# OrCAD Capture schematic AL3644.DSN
size D
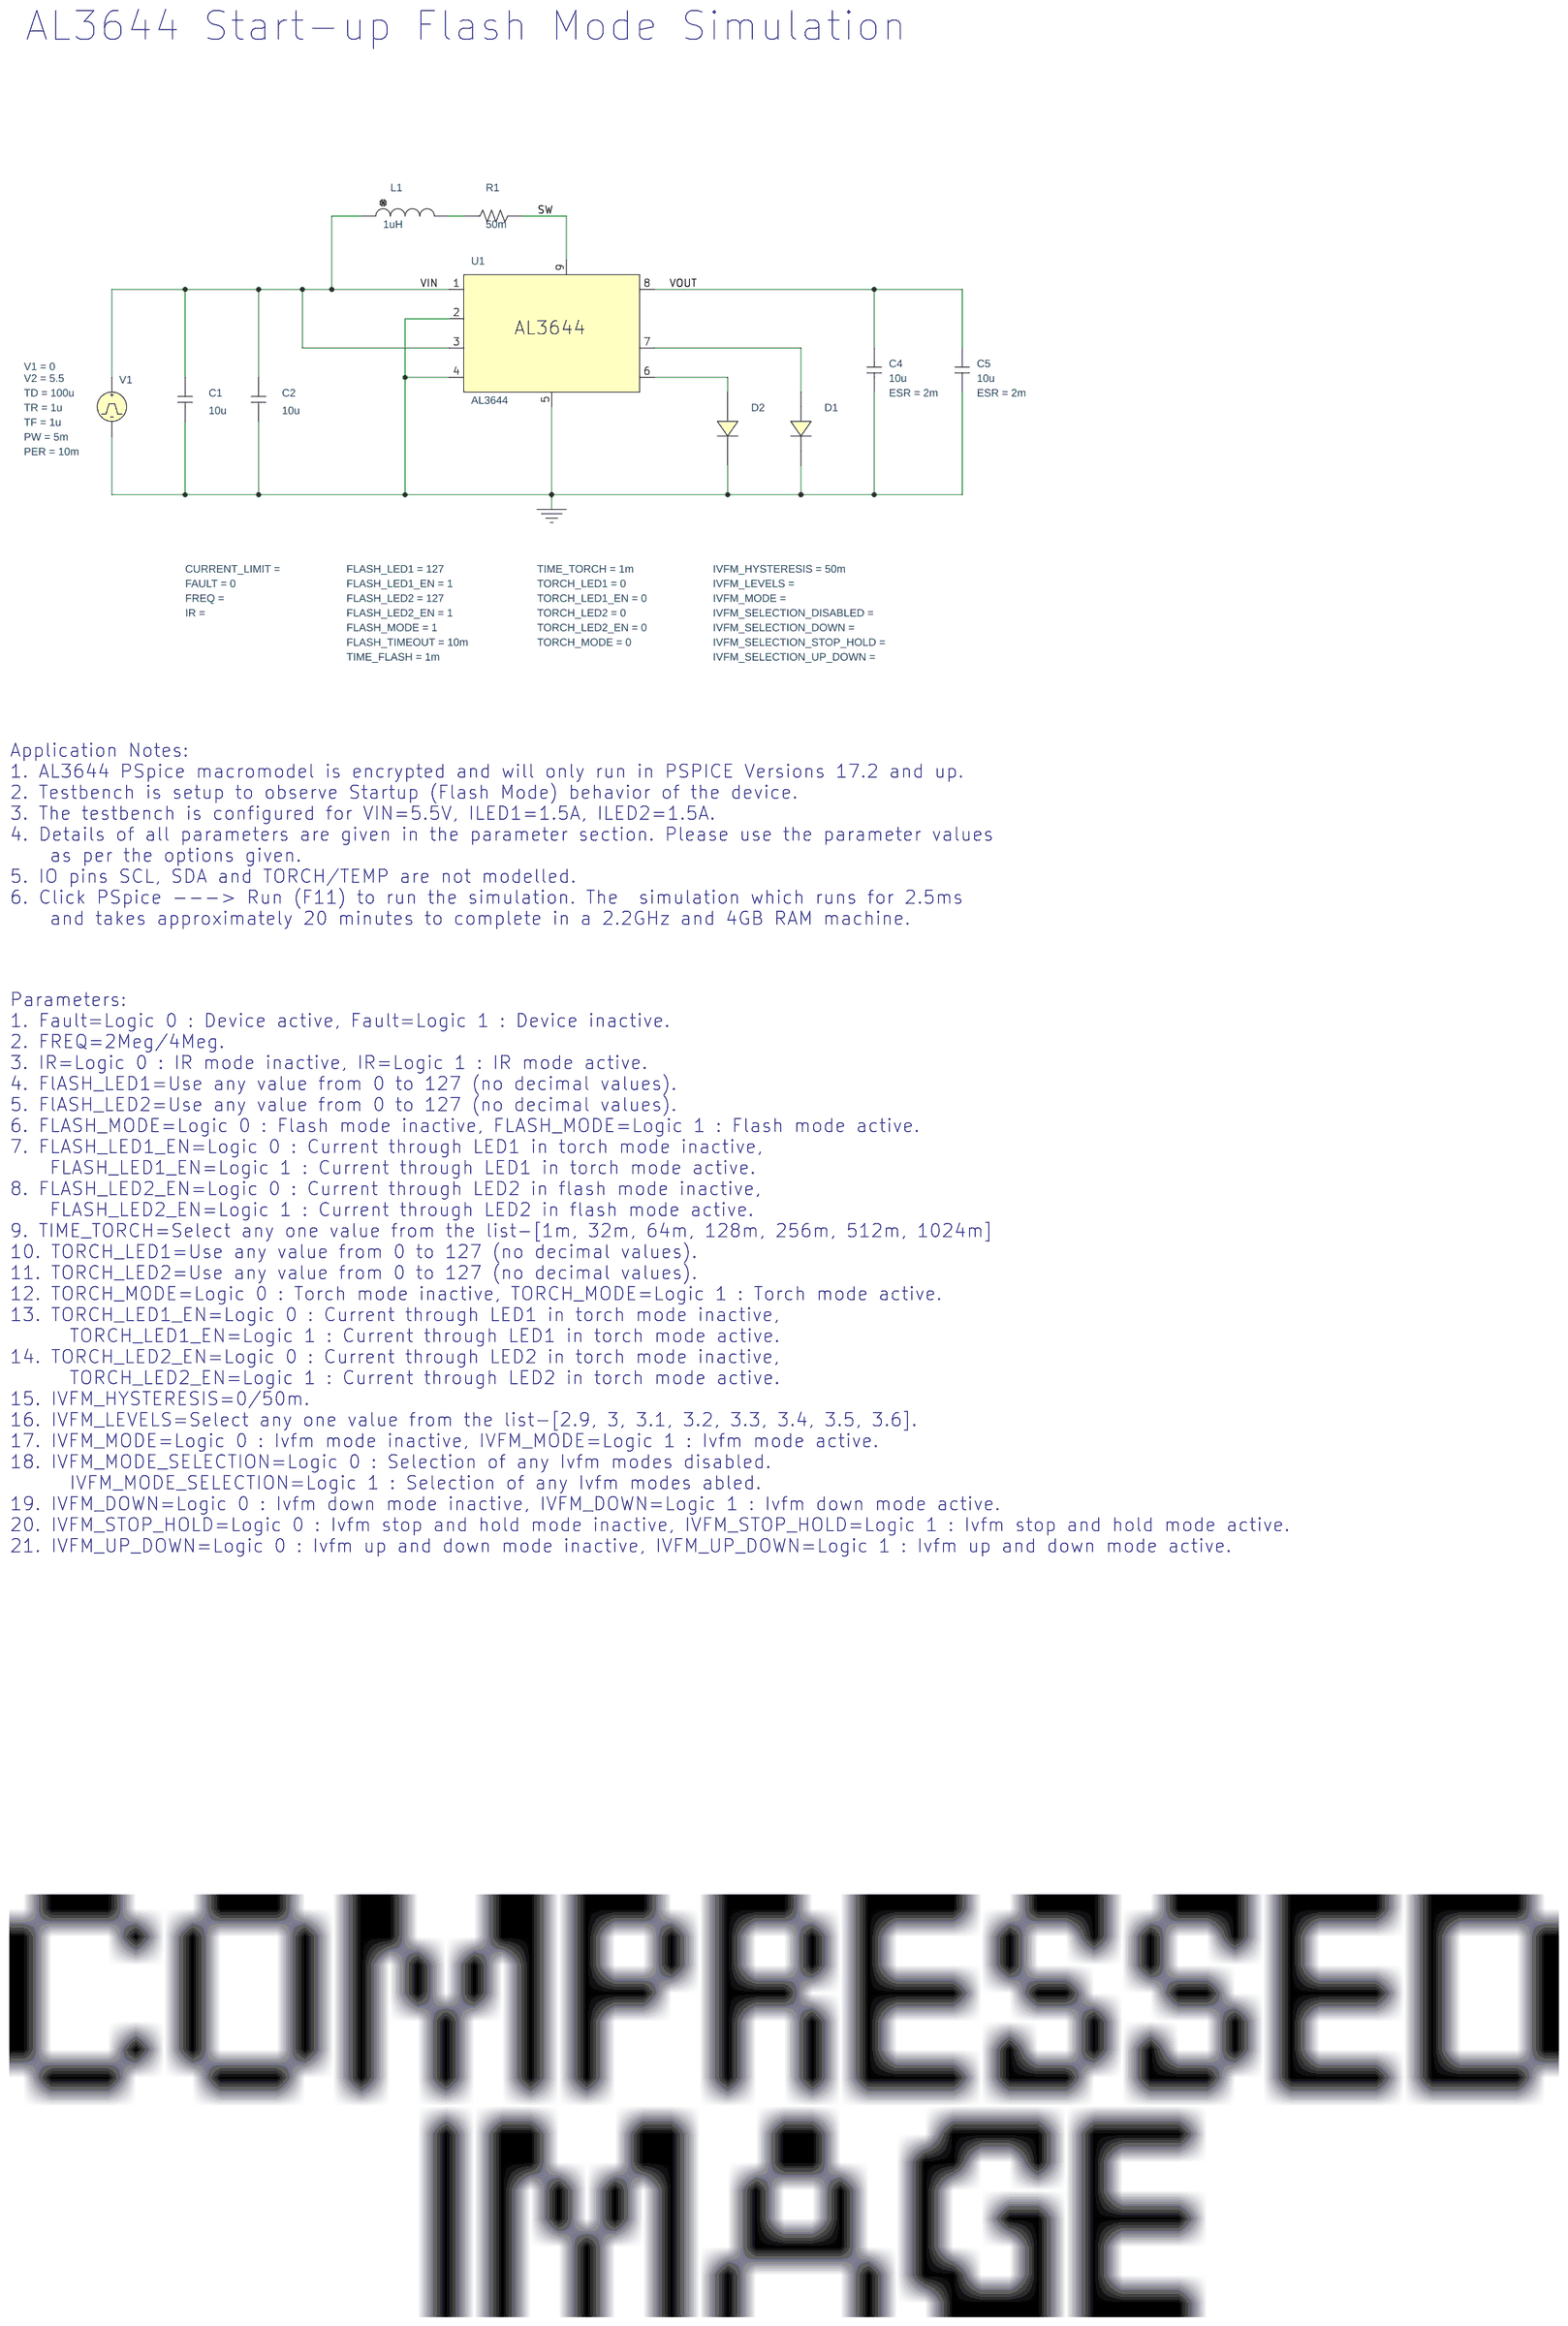
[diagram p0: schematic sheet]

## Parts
C1  10u  [cap196]
C2  10u  [cap196]
C4  10u  [RAD/CK05]
C5  10u  [RAD/CK05]
D1  LED
D2  LED
L1  1uH  [DISC350x175LS200x100034]
R1  50m  [AXRC05]
U1  AL3644
V1  VPULSE

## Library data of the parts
C1 C2 = C
C4 C5 = C: AppProp: InductiveSlave:;SRF:;PrevCap:220;PrevESL:; ESR: 2m
D1 D2 = D_D1
L1 = L
R1 = R
U1 = AL3644: FAULT: 0; FLASH_LED1: 127; FLASH_LED1_EN: 1; FLASH_LED2: 127; FLASH_LED2_EN: 1; FLASH_MODE: 1; FLASH_TIMEOUT: 10m; IVFM_HYSTERESIS: 50m; TIME_FLASH: 1m; TIME_TORCH: 1m; TORCH_LED1: 0; TORCH_LED1_EN: 0; TORCH_LED2: 0; TORCH_LED2_EN: 0; TORCH_MODE: 0
V1 = VPULSE: PER: 10m; PW: 5m; TD: 100u; TF: 1u; TR: 1u; V1: 0; V2: 5.5

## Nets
VIN: C1.1 C2.1 L1.1 U1.1(IN) U1.3(HWEN) V1.1(+)
0: C1.2 C2.2 C4.2 C5.2 D1.1(C) D2.1(C) U1.2(STROBE) U1.4(TX) U1.5(GND) V1.2(-)
SW: R1.2 U1.9(SW)
VOUT: C4.1 C5.1 U1.8(OUT)
N16076148: L1.2 R1.1
N16076360: D1.2(A) U1.7(LED1)
N16076424: D2.2(A) U1.6(LED2)

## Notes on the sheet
- AL3644 Start-up Flash Mode Simulation
- Application Notes:
  1. AL3644 PSpice macromodel is encrypted and will only run in PSPICE Versions 17.2 and up.
  2. Testbench is setup to observe Startup (Flash Mode) behavior of the device.
  3. The testbench is configured for VIN=5.5V, ILED1=1.5A, ILED2=1.5A.
  4. Details of all parameters are given in the parameter section. Please use the parameter values
      as per the options given.
  5. IO pins SCL, SDA and TORCH/TEMP are not modelled.
  6. Click PSpice ---> Run (F11) to run the simulation. The  simulation which runs for 2.5ms
      and takes approximately 20 minutes to complete in a 2.2GHz and 4GB RAM machine.
- Parameters:
  1. Fault=Logic 0 : Device active, Fault=Logic 1 : Device inactive.
  2. FREQ=2Meg/4Meg.
  3. IR=Logic 0 : IR mode inactive, IR=Logic 1 : IR mode active.
  4. FlASH_LED1=Use any value from 0 to 127 (no decimal values).
  5. FlASH_LED2=Use any value from 0 to 127 (no decimal values).
  6. FLASH_MODE=Logic 0 : Flash mode inactive, FLASH_MODE=Logic 1 : Flash mode active.
  7. FLASH_LED1_EN=Logic 0 : Current through LED1 in torch mode inactive,
      FLASH_LED1_EN=Logic 1 : Current through LED1 in torch mode active.
  8. FLASH_LED2_EN=Logic 0 : Current through LED2 in flash mode inactive,
      FLASH_LED2_EN=Logic 1 : Current through LED2 in flash mode active.
  9. TIME_TORCH=Select any one value from the list-[1m, 32m, 64m, 128m, 256m, 512m, 1024m]
  10. TORCH_LED1=Use any value from 0 to 127 (no decimal values).
  11. TORCH_LED2=Use any value from 0 to 127 (no decimal values).
  12. TORCH_MODE=Logic 0 : Torch mode inactive, TORCH_MODE=Logic 1 : Torch mode active.
  13. TORCH_LED1_EN=Logic 0 : Current through LED1 in torch mode inactive,
        TORCH_LED1_EN=Logic 1 : Current through LED1 in torch mode active.
  14. TORCH_LED2_EN=Logic 0 : Current through LED2 in torch mode inactive,
        TORCH_LED2_EN=Logic 1 : Current through LED2 in torch mode active.
  15. IVFM_HYSTERESIS=0/50m.
  16. IVFM_LEVELS=Select any one value from the list-[2.9, 3, 3.1, 3.2, 3.3, 3.4, 3.5, 3.6].
  17. IVFM_MODE=Logic 0 : Ivfm mode inactive, IVFM_MODE=Logic 1 : Ivfm mode active.
  18. IVFM_MODE_SELECTION=Logic 0 : Selection of any Ivfm modes disabled.
        IVFM_MODE_SELECTION=Logic 1 : Selection of any Ivfm modes abled.
  19. IVFM_DOWN=Logic 0 : Ivfm down mode inactive, IVFM_DOWN=Logic 1 : Ivfm down mode active.
  20. IVFM_STOP_HOLD=Logic 0 : Ivfm stop and hold mode inactive, IVFM_STOP_HOLD=Logic 1 : Ivfm stop and hold mode active.
  21. IVFM_UP_DOWN=Logic 0 : Ivfm up and down mode inactive, IVFM_UP_DOWN=Logic 1 : Ivfm up and down mode active.
